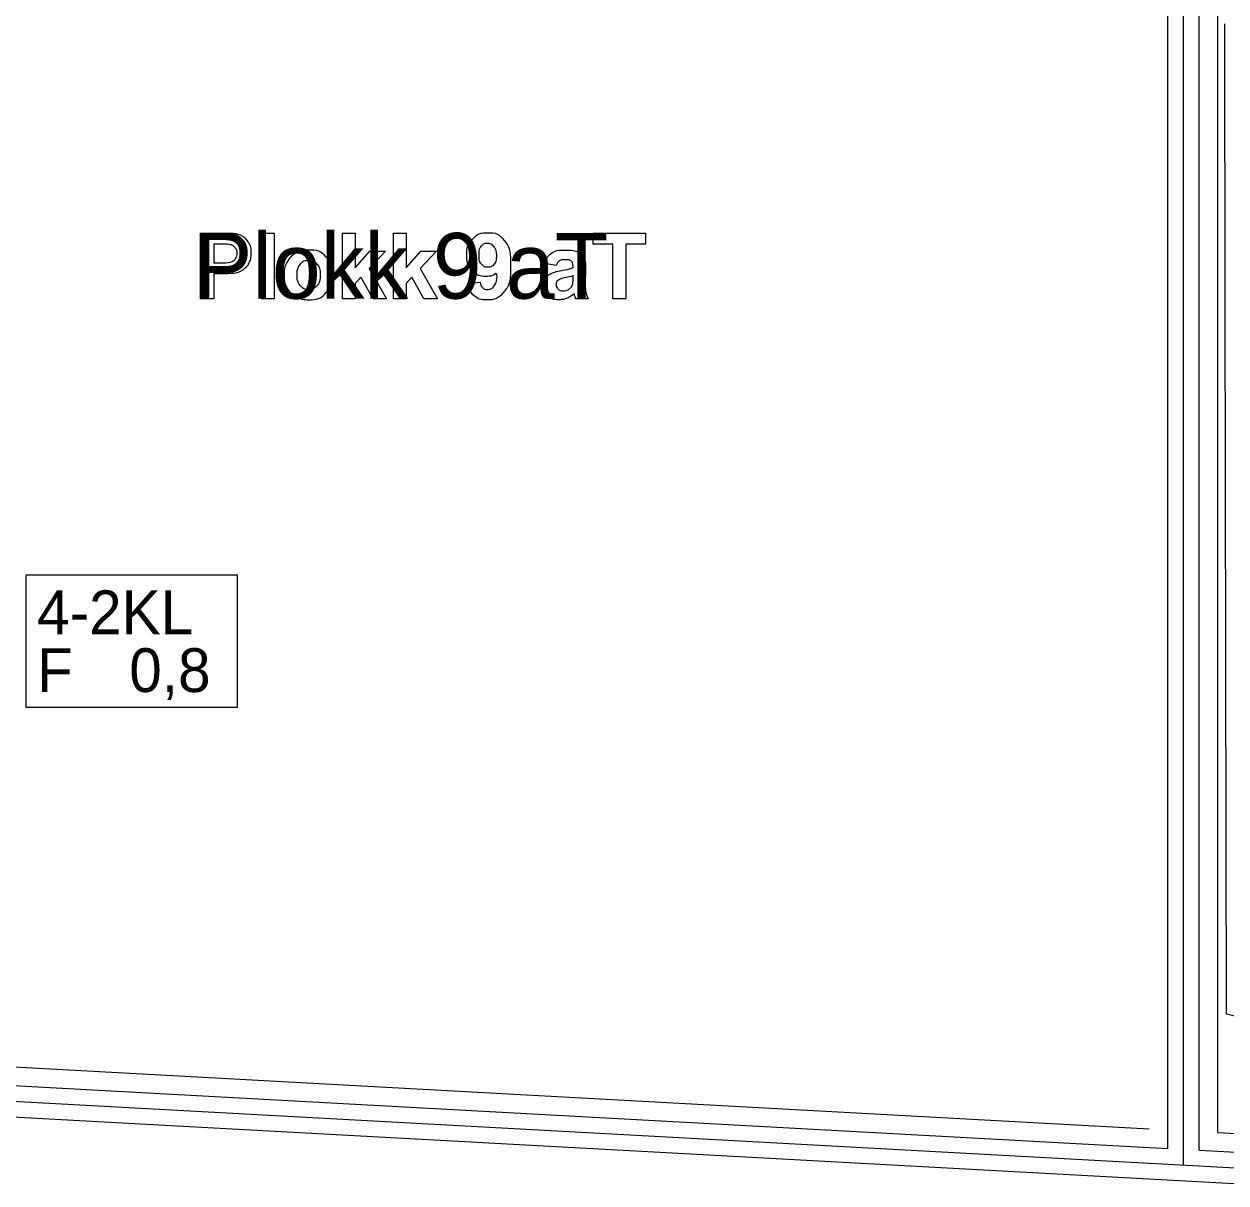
# Model space of a CAD drawing. Extents: x 532503 to 539665, y 6557663 to 6561526.
# Drawn here: x 538296.2 to 538450.1, y 6559684.2 to 6559832.5 of the extents above; entities that cross this region are included whole.
import ezdxf

# ---------------------------------------------------------------- set-up
doc = ezdxf.new("R2010")
doc.units = 0
for name, color, linetype in [('illumineerimisjooned', 7, 'Continuous'), ('PIIR', 7, 'Continuous'), ('Plokid', 7, 'Continuous'), ('Proovid', 7, 'Continuous'), ('Täide', 7, 'Continuous')]:
    doc.layers.add(name, color=color, linetype=linetype)

msp = doc.modelspace()

# ---------------------------------------------------------------- linework, layer by layer
at = {"layer": 'illumineerimisjooned'}
for p, q in [((538442.63, 6559688.61), (538442.63, 6559940)), ((538446.63, 6559688.39), (538446.63, 6559871.17))]:
    msp.add_line(p, q, dxfattribs=at)
for points in [[(538145.11, 6559687.5), (538169.44, 6559697.61), (538288.54, 6559697), (538442.63, 6559688.61)], [(538446.63, 6559688.39), (538467.83, 6559687.24), (538608.7, 6559674.2), (538713.29, 6559667.93)]]:
    msp.add_lwpolyline(points, dxfattribs=at)
at = {"layer": 'PIIR'}
msp.add_line((538444.63, 6559686.5), (538444.63, 6559940), dxfattribs=at)
msp.add_lwpolyline([(538143.11, 6559684.5), (538169.83, 6559695.6), (538288.48, 6559695), (538467.68, 6559685.24), (538608.55, 6559672.2), (538715.29, 6559665.8)], dxfattribs=at)
at = {"layer": 'Plokid'}
msp.add_line((538449.03, 6559690.66), (538449.03, 6559840.69), dxfattribs=at)
for points in [[(538318.8, 6559797.32), (538318.8, 6559805.72), (538321.52, 6559805.72)], [(538326.61, 6559797.32), (538326.61, 6559805.72), (538328.23, 6559805.72), (538328.23, 6559797.32), (538326.61, 6559797.32)], [(538336.99, 6559797.32), (538336.99, 6559805.72), (538338.6, 6559805.72), (538338.6, 6559801.26), (538340.48, 6559803.41), (538342.46, 6559803.41), (538340.38, 6559801.18), (538342.61, 6559797.32), (538340.88, 6559797.32), (538339.34, 6559800.06), (538338.6, 6559799.27), (538338.6, 6559797.32), (538336.99, 6559797.32)], [(538343.51, 6559797.32), (538343.51, 6559805.72), (538345.12, 6559805.72), (538345.12, 6559801.26), (538347, 6559803.41), (538348.99, 6559803.41), (538346.91, 6559801.18), (538349.13, 6559797.32), (538347.4, 6559797.32), (538345.87, 6559800.06), (538345.12, 6559799.27), (538345.12, 6559797.32), (538343.51, 6559797.32)], [(538371.56, 6559797.32), (538371.56, 6559804.3), (538369.07, 6559804.3), (538369.07, 6559805.72), (538375.74, 6559805.72), (538375.74, 6559804.3), (538373.26, 6559804.3), (538373.26, 6559797.32), (538371.56, 6559797.32)], [(538320.49, 6559804.3), (538320.49, 6559801.91), (538321.42, 6559801.91)], [(538321.31, 6559804.3), (538320.49, 6559804.3)], [(538321.6, 6559800.49), (538320.49, 6559800.49), (538320.49, 6559797.32), (538318.8, 6559797.32)], [(538364.33, 6559801.55), (538362.87, 6559801.81)], [(538366.49, 6559801.3), (538366.49, 6559801.46)], [(538368.08, 6559801.2), (538368.05, 6559799.32)], [(538353.04, 6559799.27), (538354.59, 6559799.45)], [(538366.49, 6559799.92), (538366.49, 6559800.25)], [(538368.42, 6559797.32), (538366.82, 6559797.32)], [(538147.51, 6559691.1), (538168.96, 6559700.01), (538288.61, 6559699.4), (538440.23, 6559691.14)], [(538143.88, 6559682.66), (538170.22, 6559693.6), (538288.42, 6559693.01), (538467.54, 6559683.25), (538608.39, 6559670.21), (538713.29, 6559663.92)], [(538449.03, 6559690.66), (538468, 6559689.63), (538608.88, 6559676.59), (538710.89, 6559670.48)]]:
    msp.add_lwpolyline(points, dxfattribs=at)
for points in [[(538321.52, 6559805.72), (538323.06, 6559805.72), (538323.53, 6559805.59), (538324.26, 6559805.4), (538324.74, 6559804.77), (538325.23, 6559804.14), (538325.23, 6559803.14), (538325.23, 6559802.36), (538324.95, 6559801.84), (538324.67, 6559801.31), (538324.24, 6559801.01), (538323.8, 6559800.71), (538323.36, 6559800.61), (538322.75, 6559800.49), (538321.6, 6559800.49)], [(538354.59, 6559799.45), (538354.65, 6559798.97), (538354.89, 6559798.74), (538355.13, 6559798.51), (538355.53, 6559798.51), (538356.03, 6559798.51), (538356.38, 6559798.97), (538356.73, 6559799.43), (538356.82, 6559800.87), (538356.22, 6559800.17), (538355.3, 6559800.17), (538354.31, 6559800.17), (538353.6, 6559800.93), (538352.88, 6559801.69), (538352.88, 6559802.92), (538352.88, 6559804.19), (538353.64, 6559804.97), (538354.39, 6559805.75), (538355.57, 6559805.75), (538356.85, 6559805.75), (538357.67, 6559804.76), (538358.49, 6559803.78), (538358.49, 6559801.51), (538358.49, 6559799.21), (538357.63, 6559798.19), (538356.78, 6559797.17), (538355.41, 6559797.17), (538354.42, 6559797.17), (538353.82, 6559797.7), (538353.21, 6559798.23), (538353.04, 6559799.27)], [(538321.42, 6559801.91), (538322.42, 6559801.91), (538322.76, 6559802.04), (538323.1, 6559802.17), (538323.29, 6559802.46), (538323.48, 6559802.74), (538323.48, 6559803.11), (538323.48, 6559803.57), (538323.21, 6559803.87), (538322.94, 6559804.17), (538322.53, 6559804.24), (538322.23, 6559804.3), (538321.31, 6559804.3)], [(538329.49, 6559800.45), (538329.49, 6559801.25), (538329.89, 6559802), (538330.29, 6559802.75), (538331.01, 6559803.15), (538331.74, 6559803.54), (538332.63, 6559803.54), (538334.02, 6559803.54), (538334.9, 6559802.65), (538335.78, 6559801.75), (538335.78, 6559800.38), (538335.78, 6559799), (538334.89, 6559798.09), (538334, 6559797.19), (538332.64, 6559797.19), (538331.81, 6559797.19), (538331.05, 6559797.56), (538330.29, 6559797.94), (538329.89, 6559798.67), (538329.49, 6559799.4), (538329.49, 6559800.45)], [(538356.68, 6559802.78), (538356.68, 6559803.56), (538356.32, 6559803.99), (538355.96, 6559804.41), (538355.49, 6559804.41), (538355.05, 6559804.41), (538354.75, 6559804.06), (538354.46, 6559803.71), (538354.46, 6559802.91), (538354.46, 6559802.1), (538354.78, 6559801.73), (538355.1, 6559801.35), (538355.58, 6559801.35), (538356.04, 6559801.35), (538356.36, 6559801.71), (538356.68, 6559802.08), (538356.68, 6559802.78)], [(538362.87, 6559801.81), (538363.12, 6559802.7), (538363.72, 6559803.12), (538364.32, 6559803.54), (538365.51, 6559803.54), (538366.59, 6559803.54), (538367.12, 6559803.29), (538367.65, 6559803.03), (538367.86, 6559802.64), (538368.08, 6559802.25), (538368.08, 6559801.2)], [(538331.15, 6559800.36), (538331.15, 6559799.46), (538331.58, 6559798.98), (538332.01, 6559798.5), (538332.64, 6559798.5), (538333.27, 6559798.5), (538333.7, 6559798.98), (538334.12, 6559799.46), (538334.12, 6559800.38), (538334.12, 6559801.27), (538333.7, 6559801.75), (538333.27, 6559802.23), (538332.64, 6559802.23), (538332.01, 6559802.23), (538331.58, 6559801.75), (538331.15, 6559801.27), (538331.15, 6559800.36)], [(538366.49, 6559801.46), (538366.49, 6559801.92), (538366.26, 6559802.12), (538366.03, 6559802.31), (538365.39, 6559802.31), (538364.96, 6559802.31), (538364.72, 6559802.14), (538364.48, 6559801.98), (538364.33, 6559801.55)], [(538366.82, 6559797.32), (538366.76, 6559797.48), (538366.67, 6559797.8), (538366.63, 6559797.94), (538366.61, 6559797.99), (538366.2, 6559797.59), (538365.73, 6559797.39), (538365.26, 6559797.19), (538364.73, 6559797.19), (538363.79, 6559797.19), (538363.25, 6559797.7), (538362.7, 6559798.21), (538362.7, 6559798.99), (538362.7, 6559799.5), (538362.95, 6559799.91), (538363.2, 6559800.31), (538363.64, 6559800.52), (538364.09, 6559800.74), (538364.92, 6559800.9), (538366.05, 6559801.11), (538366.49, 6559801.3)], [(538366.49, 6559800.25), (538366.18, 6559800.14), (538365.51, 6559800), (538364.84, 6559799.86), (538364.63, 6559799.72), (538364.32, 6559799.49), (538364.32, 6559799.15), (538364.32, 6559798.81), (538364.57, 6559798.57), (538364.82, 6559798.32), (538365.21, 6559798.32), (538365.65, 6559798.32), (538366.04, 6559798.61), (538366.33, 6559798.82), (538366.43, 6559799.14), (538366.49, 6559799.35), (538366.49, 6559799.92)], [(538368.05, 6559799.32), (538368.05, 6559798.52), (538368.13, 6559798.14), (538368.2, 6559797.76), (538368.42, 6559797.32)]]:
    msp.add_open_spline(points, degree=3, dxfattribs=at)
at = {"layer": 'Proovid'}
msp.add_lwpolyline([(538296.48, 6559762), (538323.48, 6559762), (538323.48, 6559745), (538296.48, 6559745)], close=True, dxfattribs=at)
at = {"layer": 'Täide'}
msp.add_line((538449.96, 6559796.87), (538449.9, 6559832.5), dxfattribs=at)
for points in [[(538462.82, 6559703.35), (538452.03, 6559705.3), (538450.14, 6559705.8), (538449.96, 6559796.87), (538449.9, 6559832.5)], [(538462.82, 6559703.35), (538452.03, 6559705.3), (538450.14, 6559705.8), (538449.96, 6559796.87)]]:
    msp.add_lwpolyline(points, dxfattribs=at)

# ---------------------------------------------------------------- texts
at = {"layer": 'Plokid'}
msp.add_text('Plokk 9 aT', height=8.4, dxfattribs=at).set_placement((538317.94, 6559797.32))
at = {"layer": 'Proovid'}
for s, p in [('4-2KL', (538297.88, 6559754.4)), ('F', (538297.88, 6559747)), ('0,8', (538309.68, 6559747))]:
    msp.add_text(s, height=5.6, dxfattribs=at).set_placement(p)

doc.saveas('drawing.dxf')
